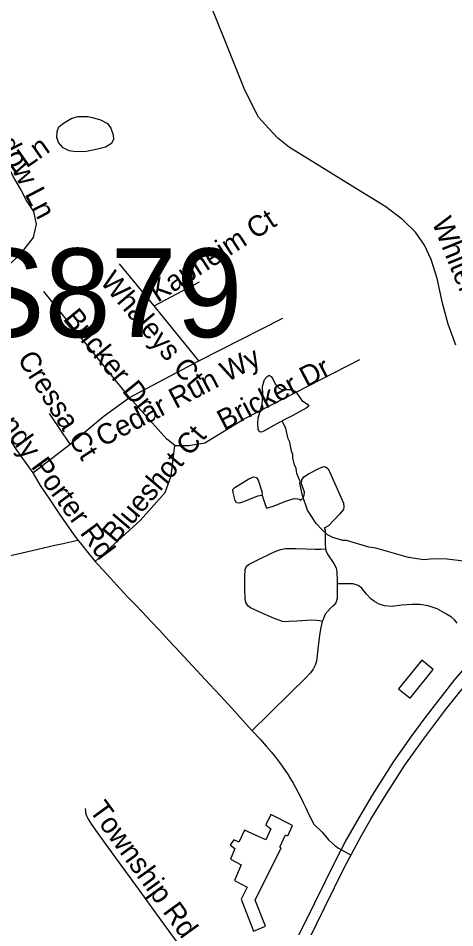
# Model space of a CAD drawing. Extents: x 1383679 to 1536984, y 460658 to 651027.
# Drawn here: x 1418729 to 1420749, y 509221 to 513426 of the extents above; entities that cross this region are included whole.
import ezdxf

# ---------------------------------------------------------------- set-up
doc = ezdxf.new("R2010")
doc.units = 0
for name, color, linetype in [('Default', 7, 'Continuous'), ('Exist Cultural Warehouse Building Footprint', 7, 'Continuous'), ('Exist Hydrographic Misc Water Feature', 7, 'Continuous'), ('Exist Road Non-System Type 51', 7, 'Continuous'), ('Exist Road Non-System Type 51 Label', 7, 'Continuous'), ('Exist Road Primary Interstate Structure Ovrhead Sign Number Label', 7, 'Continuous'), ('Exist Road Primary NC Divided Attributed', 7, 'Continuous')]:
    doc.layers.add(name, color=color, linetype=linetype)

msp = doc.modelspace()

# ---------------------------------------------------------------- linework, layer by layer
at = {"layer": 'Default'}
msp.add_lwpolyline([(1419050.8, 512972.2), (1419072.7, 512967.6), (1419110.4, 512956.4), (1419141.9, 512939.5), (1419157.3, 512917.1), (1419168.3, 512886.8), (1419169.8, 512866.7), (1419161.2, 512847), (1419132.7, 512829.8), (1419096.5, 512820.9), (1419044.2, 512810.4), (1418996.1, 512807.8), (1418964.2, 512812.7), (1418936.6, 512827.5), (1418915.3, 512852.1), (1418908, 512874.3), (1418908.8, 512902.3), (1418917.5, 512924), (1418938, 512941.5), (1418976.6, 512964.3), (1419006.9, 512971.5), (1419050.8, 512972.2)], dxfattribs=at)
at = {"layer": 'Exist Cultural Warehouse Building Footprint'}
for points in [[(1420488.5, 510326.5), (1420542.2, 510282.8), (1420649.9, 510415), (1420596.2, 510458.7), (1420488.5, 510326.5)], [(1419776.4, 509673.2), (1419749.5, 509617.6), (1419727.3, 509627.8), (1419709.8, 509605.1), (1419732, 509588.1), (1419710.9, 509539.3), (1419760.1, 509513.2), (1419729.7, 509440.6), (1419788.1, 509408.9), (1419760.1, 509354.4), (1419818.5, 509205.8), (1419873.5, 509228.5), (1419825.5, 509348.7), (1419946, 509590.4), (1419939, 509594.9), (1419965.8, 509651.6), (1419976.4, 509647.1), (1419998.6, 509694.7), (1419898, 509745.8), (1419874.6, 509698.1), (1419898, 509678.8), (1419874.6, 509627.8), (1419776.4, 509673.2)]]:
    msp.add_lwpolyline(points, dxfattribs=at)
at = {"layer": 'Exist Hydrographic Misc Water Feature'}
for points in [[(1419950.3, 511565.6), (1419947.7, 511562.5), (1419939.6, 511558.7), (1419858.7, 511514.5), (1419850.7, 511512.7), (1419842.8, 511516.9), (1419839, 511526.9), (1419837.5, 511553), (1419840.1, 511576.9), (1419857.4, 511640.5), (1419860.5, 511688.4), (1419859.3, 511724.4), (1419868, 511756.2), (1419880.3, 511769.9), (1419890.5, 511775.5), (1419900, 511769.3), (1419906.9, 511759.6), (1419909.8, 511751.3), (1419921.4, 511731), (1419937.1, 511716.7), (1419950.9, 511710.3), (1419991, 511709.4), (1420006.8, 511703.1), (1420014.7, 511696.9), (1420041.9, 511658.3), (1420067.5, 511641.8), (1420074.1, 511632.7), (1420061.1, 511623.9), (1420000.3, 511589.3), (1419950.3, 511565.6)], [(1420789.9, 510915.8), (1420713.8, 510924.9), (1420650.1, 510926.9), (1420605.4, 510922.4), (1420534.3, 510933.6), (1420383.2, 510976.9), (1420351.3, 510981.6), (1420247.9, 511012), (1420231.9, 511012.3), (1420184.2, 511025.4), (1420160.5, 511037.9), (1420135, 511060.5), (1420107.6, 511091.1), (1420066.9, 511152), (1420044.3, 511220.5), (1420032.3, 511276.7), (1420033.8, 511284.7), (1420018.6, 511321), (1420015.1, 511345), (1420007.4, 511361.2), (1420000.1, 511393.4), (1420000.4, 511409.4), (1419992.9, 511425.5), (1419985.7, 511465.7), (1419978, 511481.8), (1419967, 511530.1), (1419950.3, 511565.6)]]:
    msp.add_lwpolyline(points, dxfattribs=at)
at = {"layer": 'Exist Road Non-System Type 51'}
for points in [[(1420753.8, 511915.5), (1420719.3, 512012.5), (1420691.7, 512109.5), (1420667.6, 512223.3), (1420640, 512310.2), (1420609, 512377.2), (1420567.6, 512437.4), (1420509, 512494.2), (1420429.7, 512554.4), (1420253.9, 512661.5), (1420091.9, 512761.8), (1419985, 512828.7), (1419929.9, 512872.2), (1419888.5, 512915.7), (1419840.3, 512969.2), (1419778.2, 513093), (1419688.6, 513317.1), (1419619.6, 513484.4)], [(1418519.9, 513022.8), (1418625.6, 512846.5), (1418712.6, 512679.2), (1418742.7, 512629), (1418769.4, 512578.8), (1418799.5, 512532), (1418811.9, 512473.4), (1418798.1, 512413.2), (1418736, 512334.6), (1418632.3, 512234.2), (1418457.9, 512086.1)], [(1419565.3, 511842.7), (1419357.9, 512097), (1419197.4, 512291.1)], [(1419357.9, 512097), (1419568.6, 512207.4)], [(1419454.2, 511450.6), (1419416.2, 511480.7), (1419244.3, 511672.1), (1418847.4, 512163.1)], [(1419244.3, 511672.1), (1419565.3, 511842.7), (1419953.2, 512040.1)], [(1419454.2, 511450.6), (1419516.2, 511450.6), (1419592, 511463.9), (1419774.8, 511574.3), (1420309.1, 511848.6)], [(1418796.2, 511324.1), (1418970, 511457.9), (1419127.2, 511588.4), (1419244.3, 511672.1)], [(1418970, 511457.9), (1418873.1, 511598.4)], [(1418635.2, 511560.2), (1418722.5, 511427.8), (1418796.2, 511324.1), (1418830.9, 511265.8), (1418876.1, 511198.1), (1418917, 511138.8), (1418953.3, 511084.6), (1418983.5, 511042.2), (1419005.1, 511013.4)], [(1419085.3, 510915.1), (1419295.6, 511106), (1419409.3, 511233.1), (1419436.9, 511310.1), (1419454.2, 511450.6)], [(1420037.2, 511197.9), (1420046.9, 511208.8), (1420052.6, 511221.1), (1420054.1, 511235.6), (1420046.1, 511257.3), (1420040.4, 511273.9), (1420041.1, 511292.8), (1420050.5, 511306.5), (1420071.5, 511320.2), (1420123.6, 511345.6), (1420143.1, 511353.5), (1420151.1, 511352.1), (1420161.9, 511344.8), (1420169.9, 511331.1), (1420233.5, 511185), (1420236.4, 511166.8), (1420233.5, 511155.3), (1420215.5, 511133.6), (1420164.8, 511080.1), (1420144.6, 511068.6)], [(1419858, 511220.4), (1419836.4, 511216.8), (1419810.2, 511206.7), (1419766.1, 511189.3), (1419752.4, 511185), (1419739.4, 511186.4), (1419733.6, 511197.2), (1419723.5, 511233.4), (1419722.8, 511247.2), (1419730.8, 511256.6), (1419795.9, 511296.4), (1419817.5, 511305.8), (1419832, 511303.7), (1419839.2, 511291.3), (1419856.2, 511239.1), (1419858, 511220.4)], [(1419858, 511220.4), (1419868.2, 511187.2), (1419878.1, 511161.5), (1419908.4, 511171.3), (1419967.1, 511193.8), (1419990.1, 511201.7), (1420007.2, 511205.6), (1420021.8, 511205), (1420030.2, 511203.1), (1420037.2, 511197.9)], [(1420144.6, 511068.6), (1420149, 511060.6), (1420149, 510994.7), (1420150.8, 510973.9)], [(1418597.4, 510921.4), (1418766.7, 510959.3), (1418897.7, 510989.9), (1418937.2, 510998.5), (1418962.9, 511004), (1419005.1, 511013.4)], [(1419005.1, 511013.4), (1419015, 511000.3), (1419057.2, 510948), (1419085.3, 510915.1)], [(1420136.2, 510636.7), (1420124, 510640.7), (1420108.8, 510642.7), (1420087, 510643.2), (1420018.5, 510639.3), (1419982.2, 510636.7), (1419963.8, 510636), (1419951.9, 510636.7), (1419910.4, 510653.2), (1419847.1, 510680.2), (1419803.6, 510700), (1419791, 510710.5), (1419782.5, 510725), (1419779.1, 510741.5), (1419777.2, 510785), (1419777.2, 510844.3), (1419778.5, 510878), (1419785.1, 510892.5), (1419798.2, 510903), (1419850.4, 510928.1), (1419894.5, 510949.8), (1419920.9, 510961.8), (1419944.6, 510970.2), (1419966.4, 510974.2), (1420014.5, 510975.6), (1420103.5, 510972.2), (1420130.6, 510972.2), (1420150.8, 510973.9)], [(1420150.8, 510973.9), (1420154.6, 510962.1), (1420159.6, 510948.5), (1420189.2, 510905.7), (1420199.8, 510885.2), (1420203.1, 510866.8), (1420205.1, 510826.6), (1420205.1, 510810.9)], [(1419085.3, 510915.1), (1419155.8, 510837.4), (1419201, 510788.5), (1419236.8, 510750.5), (1419269.4, 510716.1), (1419302.3, 510681.7), (1419340.1, 510641.8), (1419382.3, 510596.7), (1419425.8, 510548.9), (1419476.2, 510495.4), (1419535.6, 510431.7), (1419594.1, 510368.8), (1419663.2, 510295.1), (1419717, 510236.8), (1419770.4, 510177.6), (1419812.2, 510132.7), (1419847.9, 510094), (1419876.1, 510061.3), (1419899.2, 510034.4), (1419919.5, 510010.1), (1419938.7, 509985.4), (1419950.8, 509969), (1419964.4, 509948.9), (1419978, 509928.2), (1419989.6, 509909.9), (1420001.4, 509889.4), (1420011.8, 509870.3), (1420024.7, 509846.3), (1420034.7, 509826.2), (1420048, 509801.2), (1420056.6, 509782.8), (1420075, 509742.4), (1420097.1, 509701.3), (1420136.2, 509663.6), (1420164.3, 509627.9), (1420194, 509601.4), (1420211.3, 509590.1), (1420269.1, 509557.7)], [(1420205.1, 510810.9), (1420205.1, 510779.8), (1420204.4, 510744.2), (1420199.1, 510723.8), (1420189.9, 510713.2), (1420173.4, 510699.3), (1420149, 510671), (1420137.9, 510643.2), (1420136.2, 510636.7)], [(1420760.2, 510630.1), (1420747.9, 510644.5), (1420734.1, 510656.8), (1420711, 510670.6), (1420688.6, 510684.3), (1420667.6, 510695.2), (1420626.4, 510709.7), (1420587.4, 510716.2), (1420550.4, 510716.2), (1420503.4, 510712.5), (1420460, 510707.5), (1420424.5, 510710.3), (1420399.2, 510717.6), (1420377.5, 510729.9), (1420360.9, 510741.5), (1420341.4, 510763.2), (1420319.6, 510792.2), (1420302.2, 510804.4), (1420279.1, 510810.9), (1420248, 510810.9), (1420205.1, 510810.9)], [(1420136.2, 510636.7), (1420129.9, 510610.3), (1420123.4, 510574.8), (1420115.4, 510508.8), (1420108.8, 510454.8), (1420102.9, 510435), (1420094.2, 510417.2), (1420081.8, 510400), (1420054.8, 510373), (1419993.5, 510311.7), (1419887, 510207.8), (1419811.2, 510133.8)], [(1419038.4, 509773.5), (1419039.7, 509762.8), (1419041.1, 509753.4), (1419043.5, 509744.4), (1419046.6, 509735.7), (1419050.8, 509727), (1419068.4, 509698.3), (1419101.4, 509651.1), (1419179.3, 509545.1), (1419272.1, 509418), (1419351.7, 509307.8), (1419438.4, 509189.4), (1419528.7, 509066), (1419541.4, 509049.1), (1419627.5, 508933.3), (1419680.6, 508857.4), (1419710.8, 508829.3), (1419731.6, 508804.4), (1419745.5, 508786.5), (1419763.8, 508773.9), (1419777.2, 508763.2), (1419797.3, 508751.2), (1419820.7, 508739.6)]]:
    msp.add_lwpolyline(points, dxfattribs=at)
at = {"layer": 'Exist Road Primary NC Divided Attributed'}
for points in [[(1419459.9, 507793.5), (1419496.3, 507900.7), (1419515.4, 507959.7), (1419592.2, 508159), (1419632, 508278.5), (1419678.8, 508407.7), (1419781.9, 508669.8), (1419850.8, 508824.9), (1419923.7, 508980), (1420101.4, 509337.2), (1420198.6, 509533.9), (1420244, 509620.9), (1420306.1, 509730.1), (1420368.2, 509834.4), (1420467.6, 509990), (1420547, 510104), (1420611.8, 510192.1), (1420751.7, 510370.4), (1420877.6, 510513.6), (1420973.8, 510617.5), (1421120.1, 510763.9), (1421400.7, 511026), (1422531.5, 512049.9)], [(1419965.8, 508944.8), (1420146.8, 509314.5), (1420239.1, 509502), (1420316.4, 509645.8), (1420360.1, 509723), (1420424.9, 509827.9), (1420518.4, 509972.7), (1420604.3, 510093.7), (1420706.4, 510229.4), (1420780.9, 510321.8), (1420924.6, 510489.3), (1421016.3, 510583.3), (1421505.5, 511042.7), (1421867.1, 511380.5), (1422124.9, 511631.4), (1422492.1, 511973.3), (1422531.5, 512049.9)]]:
    msp.add_lwpolyline(points, dxfattribs=at)

# ---------------------------------------------------------------- texts
at = {"layer": 'Exist Road Non-System Type 51 Label'}
for s, rotation, p in [('Emerald Meadow Ln', 297.6726, (1418281.5, 513520.4)), ('Silver Coach Ln', 35.0864, (1418148.7, 512296.6)), ('Kapheim Ct', 32.8635, (1419374, 512110.2)), ('Whitehall Park Dr', 292.0824, (1420641.8, 512483.4)), ('Whaleys Ct', 310.1666, (1419104.2, 512206.9)), ('Bricker Dr', 309.4656, (1418932.8, 512035.4)), ('Cedar Run Wy', 27.5365, (1419119.7, 511442.6)), ('Cressa Ct', 302.4777, (1418722.5, 511851.3)), ('Bricker Dr', 27.6465, (1419681.4, 511518.5)), ('Sandy Porter Rd', 306.4048, (1418550.6, 511671.8)), ('Blueshot Ct', 49.6839, (1419180.2, 510993.1)), ('Township Rd', 305.9809, (1419054.4, 509765.1))]:
    msp.add_text(s, height=95, rotation=rotation, dxfattribs=at).set_placement(p)
at = {"layer": 'Exist Road Primary Interstate Structure Ovrhead Sign Number Label'}
msp.add_text('S879', height=410.1, dxfattribs=at).set_placement((1418485.5, 511951.8))

doc.saveas('drawing.dxf')
